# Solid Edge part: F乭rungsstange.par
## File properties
Username: bmolnar
Dokumentum tartalom típus: 0
Author: bmolnar
Last saved by: bmolnar
Revision: 77
Sűrűség: 0,000 kg/m^3
Pontosság: 0,990
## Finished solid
Body 1: solid body, 8 faces, 7 edges, 5 vertices.
  Faces by surface: cone 4, cylinder 2, plane 2
  Edges by curve: circle 7
Bounding box of the edges (mm): 8.000 x 8.000 x 57.000, from (-4, -4, -31) to (4, 4, 26).
Cylindrical faces by radius (mm): R2.067 x1, R4 x1
Conical faces (half-angle, radius in mm at the cone's reference point): 45 deg R2.217 x1, 45 deg R3.5 x1, 45 deg R3.9 x1, 59 deg R1.0335 x1
Planar faces by outward normal: +z 1, -z 1
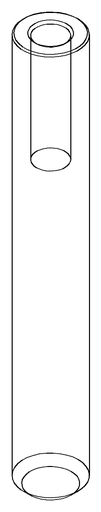
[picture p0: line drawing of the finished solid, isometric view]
